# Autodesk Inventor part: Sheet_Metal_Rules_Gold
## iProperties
Shininess: 3
Length Units: 11272
Angle Units: 11279
Time Units: 11290
Mass Units: 11286
Length Display Precision: 3
Angle Display Precision: 2
Compacted: True
Created: 2001-08
Part Number: Sheet_Metal_Rules_Gold
Material: Gold
Document SubType Name: Sheet Metal
Designer: jahraul
Density: 19.3 g/cm^3
Flat Pattern Width: 18.6512 cm
Flat Pattern Length: 26.0981 cm
Flat Pattern Area: 486.762 cm^2
Sheet Metal Rule: 18GA Gold
Density: 0.0
Volumn: 0.0
Area: 0.0
PropertySet Name: Model Information
Control State: 0
Master: False
Checked Out: False
Author: jahraul
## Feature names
1. Corner1
2. Corner2
3. Corner3
4. Corner4
5. Corner Chamfer1
6. Hole1
7. Plate1
8. Bend1
9. Plate2
10. Bend2
11. Plate3
12. Bend3
13. Plate4
14. Bend4
15. Plate5
16. Bend5
17. Cut1
18. Cut2
19. Cut3
